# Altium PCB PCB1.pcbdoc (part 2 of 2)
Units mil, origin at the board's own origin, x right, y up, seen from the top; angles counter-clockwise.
Board outline 3543.31 x 2362.2 mil, 2 copper layers (Top Layer, Bottom Layer), stack 62.206 mil thick; 105 components, 91 nets, 439 pads, 301 vias.
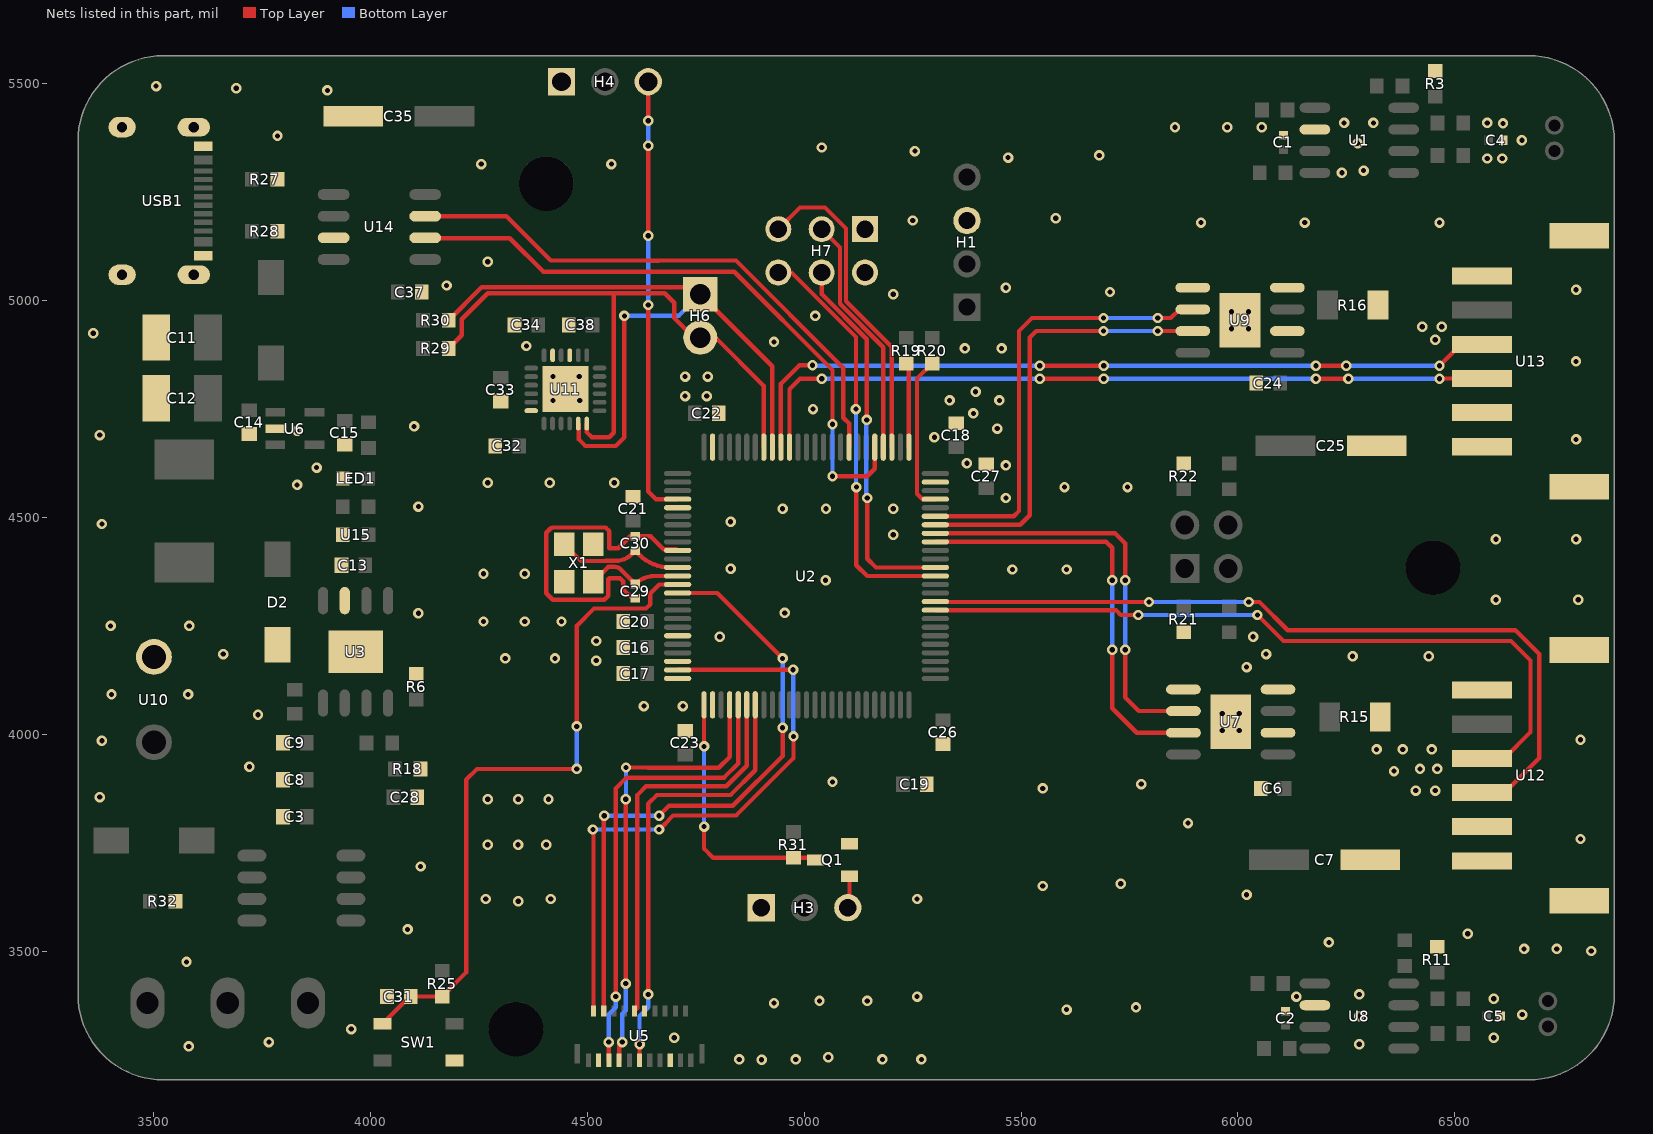
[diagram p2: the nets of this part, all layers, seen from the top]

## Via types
v1: diameter 24.02, hole 12, Top Layer to Bottom Layer, 293 vias
v2: diameter 24, hole 12, Top Layer to Bottom Layer, 8 vias

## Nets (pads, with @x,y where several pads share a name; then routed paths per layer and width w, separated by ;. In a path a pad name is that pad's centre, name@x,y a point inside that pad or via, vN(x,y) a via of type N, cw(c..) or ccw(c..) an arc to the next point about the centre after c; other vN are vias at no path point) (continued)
GND: C1.1 C2.1 C3.2 C4.2 C5.2 C6.1 C7.2 C8.2 C9.1 C11.1 C12.1 C13.1 C14.1 C15.1 C16.2 C17.1 C18.1 C19.1 C20.1 C21.1 C22.1 C23.1 C24.1 C25.2 C26.2 C27.2 C28.1 C29.1 C30.1 C31.1 C32.2 C33.2 C34.1 C35.2 C37.1 C38.1 D2.1 H1.3 H3.1 H4.1 H7.1 H7.2 LED1.2 Q1.2 R3.2 R6.1 R11.2 R15.2 R16.2 R18.1 R21.1 R22.2 R27.1 R28.1 R32.2 SW1.4 U1.2 U2.10 U2.20 U2.27 U2.74 U2.99 U3.7 U3.9 U5.12 U5.17 U6.2 U7.1 U7.9 U8.2 U9.1 U9.9 U10.1 U11.9 U11.11 U11.18 U11.25 U12.2 U12.7 U12.8 U13.2 U13.7 U13.8 U14.3 U15.1 USB1.13 USB1.14 USB1.A1B12 USB1.B1A12 X1.2 X1.4 | length 799.8
  Top Layer w10: C29.1@4610,4313.46 4603.61,4313.46 4582.07,4335 4582.07,4352.93 4575,4360 4550,4360 4548.07,4358.07 4548.07,4319.58 4538.49,4310 4420,4310 4405,4325 4405,4465 4415,4475 4416.51,4475 4418.36,4476.85 4541.64,4476.85 4550,4468.49 4550,4428.95 4571.05,4428.95 4598.64,4456.54 C30.1@4610,4456.54 4645.48,4456.54 4675.17,4426.85 4704.97,4426.85 U2.10@4707.76,4424.06
  other v1: 4901.35,3249.3 4850,3250 4980,3250 5180,3250 5270,3250 5055,3255 3580,3280 6280,3285 3765,3290 4700,3300 6590,3300 3955,3320 6280,3350 6656,3353.35 5605,3365 5765,3370 4930,3380 5035,3385 5145,3385 6590,3390.19 5260,3395 6135,3395 6280,3400 3575,3475 6815,3500 6660,3505 6735.33,3505 6210,3520 6530,3540 4085,3550 4340,3615 4265,3620 4415,3620 5260,3620 6020,3630 5550,3650 5730,3655 4115,3695 4270,3745 4339.76,3745 4405,3745 6790.16,3758.5 5885,3795 4270,3850 4340,3850 4410,3850 3375,3855 6410,3870 6455,3870 5550,3875 5777.01,3885 5065,3890 6360,3915 6420,3920 6460,3920 3720,3925 6320,3965 6380,3965 6447.11,3965 3380,3985 6790.16,3987.49 3740,4045 4630,4065 4720,4065 3402,4091.82 3578.6,4091.82 6020,4155 4520,4170 4310,4175 4425,4175 6264.49,4180 6440,4180 3660,4185 6065,4185 4520,4215 4805,4225 6035,4225 3400,4250 3581.6,4250 4260,4260 4355.24,4260 4440,4260 4110,4279.19 4955,4280 6595,4310 6785,4310 5049.01,4355 4260,4370 4355,4370 5480,4380 5605,4380 4830,4381.88 6595,4450 6780,4450 5205,4460 3380,4485 4830,4490 4950,4520 5050,4520 5205,4520 4110,4525 5465,4545 5600,4570 5745.43,4570 3830,4575 4270,4580 4412.73,4580 4561.61,4580 3875,4615 5465,4620 5375,4625 6780,4680 5300,4685 3375,4690 3830,4700 5445,4705 4100,4710 5390,4740 5020,4750 4420,4770 4482.14,4770 5335,4770 5450,4770 4725,4780 4775,4780 5395,4790 4420,4825 4480.88,4825 4725,4825 4777.24,4825 6779.8,4860 5370.33,4890 5455,4890 4358.93,4895.41 4930,4905 6455,4910 3360,4925 6425,4940 6470,4940 5025,4965 5205,5015 5705,5020 6780,5025 5465,5030 4175,5035 4270,5090 5915,5180 6154.21,5180 6465,5180 5250,5185 5580,5190 6240,5295 6290,5300 4255,5315 4555,5315 6575,5327.98 6609.71,5327.98 5470,5330 5680,5335 5255,5345 5040.39,5353.31 6276.06,5363.14 6655,5370 3785,5380 5855,5400 5975.36,5400 6055,5400 6611.54,5408.95 6245,5410 6312.58,5410 6575,5410 3900,5485 3690,5490 3505,5495
  other v2: 5963.82,4008.82 6003.19,4008.82 5963.82,4048.19 6003.19,4048.19 5985.31,4935.31 6024.68,4935.31 5985.31,4974.68 6024.68,4974.68
I2C1_SCL: H6.1 R30.1 U2.92 U11.23 | length 1672.6
  Top Layer w10: R30.1@4179.66,4955 4255.75,5031.09 4743.91,5031.09 H6.1@4760,5015 4926.26,4848.74 U2.92@4926.26,4662.24 ; U11.23@4478.46,4716.64 4480,4715.1 4480,4680 4495,4665 4565,4665 4585,4685 v1(4585,4965)
  Bottom Layer w10: v1(4585,4965) 4710,4965 H6.1@4760,5015
I2C1_SDA: H6.2 R29.1 U2.93 U11.24 | length 1464.3
  Top Layer w10: R29.1@4179.66,4890 4210,4920.34 4210,4957.07 4270,5017.07 4560.28,5017.07 ; U11.24@4498.14,4716.64 4497.93,4716.44 4497.93,4697.07 4510,4685 4550,4685 4560.28,4695.28 4560.28,5017.07 ; U2.93@4906.57,4662.24 4906.57,4803.43 4795,4915 H6.2@4760,4915 4745,4915 4700,4960 4700,4995 4677.93,5017.07 4560.28,5017.07
LED-(背光开关): U2.24 U5.2 | length 1421.3
  Top Layer w10: v1(4512.27,3780.23) 4513.7,3778.79 U5.2@4513.7,3361.59 ; v1(4665,3780.23) 4673.8,3789.03 4674.52,3789.03 4687.99,3802.49 4687.99,3803.22 4697.4,3812.63 4842.63,3812.63 4975,3945 v1(4975,3995) ; U2.24@4707.76,4148.46 4765,4148.46 4765.33,4148.79 v1(4974.21,4148.79)
  Bottom Layer w10: v1(4512.27,3780.23) v1(4665,3780.23) ; v1(4974.21,4148.79) 4974.21,3995.79 v1(4975,3995)
MOTOR1_IN1: U2.68 U7.2 | length 950
  Top Layer w10: U2.68@5302.24,4463.43 5716.57,4463.43 5740,4440 v1(5740,4355) ; v1(5740,4195) 5740,4085 5771.49,4053.51 U7.2@5874.49,4053.51
  Bottom Layer w10: v1(5740,4195) v1(5740,4355)
MOTOR1_IN2: U2.67 U7.3 | length 971.3
  Top Layer w10: U2.67@5302.24,4443.74 5696.26,4443.74 5710,4430 v1(5710,4355) ; v1(5710,4195) 5710,4060 5766.49,4003.51 U7.3@5874.49,4003.51
  Bottom Layer w10: v1(5710,4195) v1(5710,4355)
MOTOR1_OUT1: U7.6 U12.1
MOTOR1_OUT2: U7.8 U12.6
MOTOR2_IN1: U2.70 U9.2 | length 1034.5
  Top Layer w10: U2.70@5302.24,4502.8 5482.8,4502.8 5495,4515 5495,4930 5525,4960 v1(5690,4960) ; v1(5815,4960) 5845,4960 5865,4980 U9.2@5895.98,4980
  Bottom Layer w10: v1(5690,4960) v1(5815,4960)
MOTOR2_IN2: U2.69 U9.3 | length 1019
  Top Layer w10: U2.69@5302.24,4483.11 5498.11,4483.11 5520,4505 5520,4915 5535,4930 v1(5690,4930) ; v1(5815,4930) U9.3@5895.98,4930
  Bottom Layer w10: v1(5690,4930) v1(5815,4930)
MOTOR2_OUT1: U9.6 U13.1
MOTOR2_OUT2: U9.8 U13.6
OSC_IN: C30.2 U2.12 X1.1 | length 296.5
  Top Layer w10: X1.1@4446.53,4438.31 4485.08,4399.77 4541.64,4399.77 4541.87,4400 4565,4400 ccw(c4565,4452) 4601.77,4415.23 C30.2@4610,4423.46 4619.49,4413.97 ccw(c4690.2,4484.68) 4690.2,4384.68 U2.12@4707.76,4384.68
OSC_OUT: C29.2 U2.13 X1.3 | length 228.9
  Top Layer w10: X1.3@4513.47,4351.69 4547.76,4385.98 4562.62,4385.98 cw(c4562.62,4366.83) 4576.16,4380.38 C29.2@4610,4346.54 cw(c4654.57,4301.97) 4654.57,4365 U2.13@4707.76,4365
RST: C31.2 R25.1 SW1.1 U2.14 | length 1568.5
  Top Layer w10: SW1.1@4027.32,3332.32 4090,3395 4164.66,3395 R25.1@4165,3395.34 4220,3450.34 4220,3895 4245,3920 v1(4475,3920) ; v1(4475,4017.99) 4475,4250 4515,4290 4635,4290 4645,4300 4645,4325 4665.31,4345.31 U2.14@4707.76,4345.31
  Bottom Layer w10: v1(4475,3920) v1(4475,4017.99)
RST_MONITOR: U2.15 U5.4 | length 1449.2
  Top Layer w10: U5.4@4537.32,3361.59 4537.32,3810.78 v1(4538.56,3812.02) ; v1(4665,3812.02) 4687.98,3835 4835,3835 4950,3950 v1(4950,4015) ; U2.15@4707.76,4325.63 4799.37,4325.63 v1(4950,4175)
  Bottom Layer w10: v1(4538.56,3812.02) v1(4665,3812.02) ; v1(4950,4015) v1(4950,4175)
SBUS: H3.3 Q1.1 | length 79.2
  Top Layer w10: H3.3@5100.39,3600 5104.37,3603.98 Q1.1@5104.37,3677.6
SPI1_MISO: U2.31 U5.10 | length 921.8
  Top Layer w10: U5.10@4608.19,3361.59 4614.92,3368.33 4614.92,3859.92 4635,3880 4820,3880 4867.2,3927.2 U2.31@4867.2,4067.76
SPI1_MOSI: U2.32 U5.11 | length 1029.5
  Top Layer w10: U5.11@4620,3248.41 v1(4620,3285) ; v1(4640,3400) 4640,3840 4660,3860 4830,3860 4886.89,3916.89 U2.32@4886.89,4067.76
  Bottom Layer w10: v1(4620,3285) 4620,3350 4640,3370 v1(4640,3400)
SPI1_NSS: U2.29 U5.7 | length 1056
  Top Layer w10: U5.7@4572.76,3248.41 4572.76,3282.76 v1(4580,3290) ; v1(4587.99,3425) v1(4587.99,3850) ; v1(4588.74,3923.27) 4638.74,3923.27 4639.18,3922.83 4802.83,3922.83 4827.83,3947.83 U2.29@4827.83,4072.76
  Bottom Layer w10: v1(4580,3290) 4580,3355 4587.99,3362.99 v1(4587.99,3425) ; v1(4587.99,3850) 4588.74,3850.75 v1(4588.74,3923.27)
SPI1_SCK: U2.30 U5.5 | length 1074.9
  Top Layer w10: v1(4548.9,3290) 4548.9,3248.64 U5.5@4549.13,3248.41 ; v1(4565,3395) 4565,3875 4590,3900 4815,3900 4847.52,3932.52 U2.30@4847.52,4067.76
  Bottom Layer w10: v1(4548.9,3290) 4548.9,3353.9 4565,3370 v1(4565,3395)
SWCLK: R19.2 U2.76 | length 195.7
  Top Layer w10: R19.2@5235,4855.34 5241.22,4849.12 U2.76@5241.22,4662.24
SWDIO: R20.2 U2.72 | length 362.8
  Top Layer w10: R20.2@5295,4855.34 5260,4820.34 5260,4608.46 5259.76,4608.22 5259.76,4554.85 5272.44,4542.17 U2.72@5302.24,4542.17
TE: U5.3
TIM3_CH1: U2.90 U13.3 | length 1740.9
  Top Layer w10: U2.90@4965.63,4662.24 4965.63,4795.63 4990,4820 v1(5040,4820) ; v1(5542.99,4820) v1(5690.6,4820) ; v1(6180,4820) v1(6255,4820) ; v1(6465,4820) 6465.63,4820.63 U13.3@6562.8,4820.63
  Bottom Layer w10: v1(5040,4820) v1(5542.99,4820) ; v1(5690.6,4820) v1(6180,4820) ; v1(6255,4820) v1(6465,4820)
TIM3_CH2: U2.91 U13.4 | length 1801.7
  Top Layer w10: U2.91@4945.94,4662.24 4945.94,4808.46 4988.7,4851.21 v1(5018.79,4851.21) ; v1(5542.99,4850) v1(5690.6,4850) ; v1(6180,4850) v1(6250,4850) ; v1(6465,4850) 6514.37,4899.37 U13.4@6562.8,4899.37
  Bottom Layer w10: v1(5018.79,4851.21) 5020,4850 v1(5542.99,4850) ; v1(5690.6,4850) v1(6180,4850) ; v1(6250,4850) v1(6465,4850)
TIM4_CH1: U2.60 U12.3 | length 1847.9
  Top Layer w10: U2.60@5302.24,4305.94 5303.18,4305 v1(5795,4305) ; v1(6025,4305) 6050,4305 6115,4240 6640,4240 6695,4185 6695,3945 6615.63,3865.63 U12.3@6562.8,3865.63
  Bottom Layer w10: v1(5795,4305) v1(6025,4305)
TIM4_CH2: U2.59 U12.4 | length 1723.2
  Top Layer w10: U2.59@5302.24,4286.26 5718.74,4286.26 5730,4275 v1(5770,4275) ; v1(6045,4275) 6105,4215 6630,4215 6675,4170 6675,4005 6614.37,3944.37 U12.4@6562.8,3944.37
  Bottom Layer w10: v1(5770,4275) v1(6045,4275)
TIM9_CH1: H4.3 U2.4 | length 1020.1
  Top Layer w10: v1(4640,4990) 4640,4560 4657.83,4542.17 U2.4@4707.76,4542.17 ; v1(4640,5150) v1(4640,5357.4) ; v1(4640,5415) H4.3@4640,5505
  Bottom Layer w10: v1(4640,4990) v1(4640,5150) ; v1(4640,5357.4) v1(4640,5415)
TIM9_CH2: U2.5
UART5_RX: U2.83 U14.7 | length 1298.1
  Top Layer w10: U14.7@4125.61,5195 4312.43,5195 4414.93,5092.5 4644.98,5092.5 4645.48,5092.01 4664.52,5092.01 4665.02,5092.5 4842.5,5092.5 5090,4845 5090,4730 5103.43,4716.57 U2.83@5103.43,4662.24
UART5_TX: U2.80 U14.6 | length 1465.2
  Top Layer w10: U14.6@4125.61,5145 4126.43,5144.18 4320.82,5144.18 4398.18,5066.82 4838.18,5066.82 5065,4840 v1(5065,4715) ; v1(5065,4595) 5144.96,4595 5162.48,4612.52 U2.80@5162.48,4662.24
  Bottom Layer w10: v1(5065,4595) v1(5065,4715)
USART2_RX: Q1.3 R31.1 U2.26 | length 597.2
  Top Layer w10: v1(4768.78,3787.01) 4768.78,3736.22 4789.66,3715.34 R31.1@4975,3715.34 5025.29,3715.34 Q1.3@5025.63,3715 ; v1(4768.78,3972.01) U2.26@4768.78,4067.76
  Bottom Layer w10: v1(4768.78,3787.01) v1(4768.78,3972.01)
USART2_TX: U2.25
USART3_RX: H7.3 U2.79 | length 561.6
  Top Layer w10: H7.3@5040,5165 5082.16,5122.84 5082.16,4992.84 5182.17,4892.83 U2.79@5182.17,4662.24
USART3_TX: H7.5 U2.78 | length 745.1
  Top Layer w10: H7.5@4940,5165 4990,5215 5047.85,5215 5096.17,5166.68 5096.17,4998.83 5201.85,4893.15 U2.78@5201.85,4662.24
USART6_RX: H7.4 U2.64 | length 870.1
  Top Layer w10: H7.4@5040,5065 5040,5015.18 5144.14,4911.04 v1(5144.14,4725) ; v1(5145.06,4545) 5145.06,4404.94 5165.32,4384.68 U2.64@5302.24,4384.68
  Bottom Layer w10: v1(5144.14,4725) 5142.99,4723.85 5142.99,4547.07 v1(5145.06,4545)
USART6_TX: H7.6 U2.63 | length 959.9
  Top Layer w10: H7.6@4940,5065 4970.36,5065 5119.08,4916.28 v1(5119.08,4750) ; v1(5120,4570) 5120,4390 5145,4365 U2.63@5302.24,4365
  Bottom Layer w10: v1(5119.08,4750) 5119.08,4570.92 v1(5120,4570)
WKUP: U2.23
pads on no net: SCREW1.1 SCREW2.1 SCREW3.1 SW1.2 SW1.3 U2.1 U2.2 U2.3 U2.9 U2.16 U2.17 U2.18 U2.33 U2.35 U2.36 U2.38 U2.39 U2.40 U2.41 U2.42 U2.43 U2.44 U2.45 U2.46 U2.47 U2.53 U2.54 U2.55 U2.56 U2.57 U2.58 U2.61 U2.62 U2.65 U2.66 U2.71 U2.77 U2.81 U2.82 U2.84 U2.85 U2.86 U2.87 U2.88 U2.89 U2.98 U5.6 U5.15 U5.16 U5.18 U5.19 U5.20 U5.21 U5.22 U5.23 U6.4 U11.1 U11.2 U11.3 U11.4 U11.5 U11.6 U11.7 U11.12 U11.14 U11.15 U11.16 U11.17 U11.19 U11.21 U11.22 U14.4 USB1.A8 USB1.B8

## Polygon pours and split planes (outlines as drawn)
BAT on Top Layer (solid, remove dead copper, pour order 0): 3435,4010 3485,4060 3595,4060 3640,4015 3640,3848.2 3775,3713.2 3870.48,3516.34 3870.48,3464.51 3900,3434.99 3900,3333.17 3881.83,3315 3845,3315 3774.26,3333.17 3774.26,3555.85 3753.69,3600 3690,3600 3435,3855
12V on Top Layer (solid, remove dead copper, pour order 2): 3930,3545 3930,3551.14 3825.74,3770.74 3825,4001.05 3843.95,4020 3895,4020 3920,4045 3920,4100 3935,4115 3990,4115 4010,4095 4010,3955 3950,3895 3950,3795 4035,3710 4035,3590 3990,3545
$1N321 on Top Layer (solid, remove dead copper, pour order 6): 3620,3510 3696.56,3586.56 3761.26,3586.56 3761.26,3550.01 3760,3548.75 3760,3335 3732.79,3307.79 3657.21,3307.79 3620,3345
$1N322 on Top Layer (solid, remove dead copper, pour order 8): 3405,3315 3350,3370 3350,3780 3361.3,3791.3 3436.61,3791.3 3535,3692.92 3535,3335 3515,3315
$1N58 on Top Layer (solid, remove dead copper, pour order 12): 3910,4265 3905,4270 3805,4270 3745,4330 3500,4330 3475,4355 3475,4430 3503.52,4458.52 3806.48,4458.52 3910,4355
5V on Top Layer (solid, remove dead copper, pour order 14): 3805,4680 3805,4615 3750,4560 3514.05,4560 3492.01,4582.05 3492.01,4681.96 3520.04,4710 3565,4710 3565,4976.82 3593.18,5005 3765,5005 3820.64,4949.36 3820.64,4750.64 3795,4725 3685,4725 3685,4665 3745,4665 3760,4680
3V3 on Top Layer (solid, remove dead copper, pour order 18): 3845,4730 3845,4755 3918.99,4828.99 4021.01,4828.99 4021.01,4706.78 4014.23,4700 3914.41,4700 3884.41,4730
BAT_ADC on Top Layer (solid, remove dead copper, pour order 20): 4020,4007.92 4020,3827.04 4080,3827.04 4080,4007.92
MOTOR2_OUT2 on Top Layer (solid, remove dead copper, pour order 22): 6075,5015 6075,5065 6105,5095 6630,5095 6645,5080 6645,5035 6625,5015
MOTOR2_OUT1 on Top Layer (solid, remove dead copper, pour order 24): 6070,4910 6070,4945 6078.73,4953.73 6078.73,4954.91 6370.09,4954.91 6485,4800.33 6485,4715.76 6487.65,4713.1 6611.9,4713.1 6645,4680 6645,4640.33 6628.45,4623.78 6468.3,4623.78 6280,4880 6091.17,4888.83
MOTOR1_OUT2 on Top Layer (solid, remove dead copper, pour order 28): 6050,4115 6050,4135 6060,4145 6640,4145 6650,4135 6650,4085 6625,4060 6495,4060 6472.17,4082.83 6062.17,4082.83 6050,4095
MOTOR1_OUT1 on Top Layer (solid, remove dead copper, pour order 30): 6050,4020 6078.29,4030 6188.79,4030 6398,3820.79 6611.9,3758.11 6615,3755 6625,3755 6650,3730 6650,3696.02 6631.46,3677.48 6453.96,3677.48 6357.49,3722.51 6110,3970 6070,3970 6050,3990
GND on Top Layer (solid, remove dead copper, pour order 36): 3220,5680 3220,3145 6955,3145 6955,5680
GND on Bottom Layer (solid, remove dead copper, pour order 28): 3220,5665 3220,3140 6945,3140 6945,5665
GND on Top Layer (solid, remove dead copper, pour order 34): 3000,5760 3000,3000 7220,3000 7220,5760

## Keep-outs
Board Outline Layer:
  the board outline again, w10

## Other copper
Top Layer:
  region net $1N279: 3727.26,5086.88 3713.12,5072.74 3711.61,5074.13 3710.15,5075.27 3707.31,5077.12 3704.48,5078.98 3703.02,5080.12 3701.51,5081.51 3718.49,5098.49 3719.88,5096.98 3721.02,5095.52 3722.88,5092.69 3724.73,5089.85 3725.87,5088.39
  region net $1N279: 3729.1,5056.76 3717.07,5097.07 3719.77,5094.84 3722.84,5093.15 3726.17,5092.06 3729.64,5091.62 3733.14,5091.83 3736.53,5092.69 3739.7,5094.17 3739.7,5024.94 3739.4,5030.62 3738.49,5036.23 3736.98,5041.71 3734.9,5047 3732.26,5052.04 3729.1,5056.76
  region net 12V: 6127.5,4588.88 6092.5,4588.88 6092.15,4595.63 6091.11,4602.31 6089.39,4608.84 6087.01,4615.16 6083.98,4621.21 6080.35,4626.91 6076.16,4632.21 6071.44,4637.05 6066.25,4641.38 6153.75,4641.38 6148.56,4637.05 6143.84,4632.21 6139.65,4626.91 6136.02,4621.21 6132.99,4615.16 6130.61,4608.84 6128.89,4602.31 6127.85,4595.63 6127.5,4588.88
  region net 12V: 6092.5,4741.12 6127.5,4741.12 6127.85,4734.37 6128.89,4727.69 6130.61,4721.16 6132.99,4714.84 6136.02,4708.79 6139.65,4703.09 6143.84,4697.79 6148.56,4692.95 6153.75,4688.62 6066.25,4688.62 6071.44,4692.95 6076.16,4697.79 6080.35,4703.09 6083.98,4708.79 6087.01,4714.84 6089.39,4721.16 6091.11,4727.69 6092.15,4734.37 6092.5,4741.12
  region net 12V: 6127.5,4816.2 6092.5,4816.2 6092.28,4833.35 6091.92,4842.13 6091.31,4850.4 6090.4,4857.68 6089.8,4860.79 6089.11,4863.48 6088.31,4865.67 6087.4,4867.31 6086.37,4868.34 6085.8,4868.61 6085.2,4868.7 6142.84,4868.7 6141.58,4868.61 6140.39,4868.35 6139.27,4867.93 6138.22,4867.34 6137.23,4866.61 6136.3,4865.73 6134.62,4863.57 6133.16,4860.93 6131.92,4857.86 6130.87,4854.41 6129.99,4850.66 6129.28,4846.64 6128.71,4842.43 6127.96,4833.63 6127.59,4824.74
  region net 12V: 6092.5,3786.12 6127.5,3786.12 6127.85,3779.37 6128.89,3772.69 6130.61,3766.16 6132.99,3759.84 6136.02,3753.79 6139.65,3748.09 6143.84,3742.79 6148.56,3737.95 6153.75,3733.62 6066.25,3733.62 6071.44,3737.95 6076.16,3742.79 6080.35,3748.09 6083.98,3753.79 6087.01,3759.84 6089.39,3766.16 6091.11,3772.69 6092.15,3779.37 6092.5,3786.12
  region net 12V: 6127.5,3635.4 6092.5,3635.4 6092.15,3642.01 6091.11,3648.54 6089.38,3654.92 6086.99,3661.09 6083.96,3666.97 6080.33,3672.5 6076.13,3677.61 6071.42,3682.26 6066.25,3686.38 6153.75,3686.38 6148.58,3682.26 6143.87,3677.61 6139.67,3672.5 6136.04,3666.97 6133.01,3661.09 6130.62,3654.92 6128.89,3648.54 6127.85,3642.01 6127.5,3635.4
  region net 12V: 6127.5,3901.01 6092.5,3889.72 6092.34,3898.71 6092.09,3903.28 6091.7,3907.82 6091.14,3912.3 6090.39,3916.64 6089.41,3920.82 6088.18,3924.77 6086.68,3928.45 6084.87,3931.79 6082.74,3934.77 6080.26,3937.31 6078.87,3938.41 6077.39,3939.38 6075.81,3940.22 6074.12,3940.92 6072.32,3941.48 6070.41,3941.88 6068.39,3942.13 6066.25,3942.22 6132.65,3953.51 6132.43,3949.67 6131.85,3944.68 6130.08,3931.98 6129.13,3924.65 6128.31,3916.92 6127.72,3908.98
  region net $1N19: 6553.62,5365 6553.62,5375 6557.69,5375.37 6561.63,5376.45 6565.31,5378.23 6568.62,5380.63 6568.62,5359.37 6565.31,5361.77 6561.63,5363.55 6557.69,5364.63 6553.62,5365
  region net $1N19: 6578.46,5365 6571.23,5364.71 6564.04,5363.83 6556.95,5362.37 6550,5360.34 6545,5371.42 6550,5384.66 6554.21,5381.78 6558.7,5379.38 6563.43,5377.48 6568.34,5376.11 6573.37,5375.28 6578.46,5375 6578.46,5365
  region net $1N87: 6548.62,3345 6548.62,3355 6552.69,3355.37 6556.63,3356.45 6560.31,3358.23 6563.62,3360.63 6563.62,3339.37 6560.31,3341.77 6556.63,3343.55 6552.69,3344.63 6548.62,3345
  region net $1N87: 6573.46,3355 6568.35,3355.29 6563.3,3356.15 6558.38,3357.57 6553.65,3359.54 6549.17,3362.03 6545,3365 6540,3350.09 6545,3335 6549.17,3337.97 6553.65,3340.46 6558.38,3342.43 6563.3,3343.85 6568.35,3344.71 6573.46,3345 6573.46,3355
  region net I2C1_SDA: 4555.28,4982.07 4554.99,4987.42 4554.13,4992.71 4552.71,4997.88 4550.75,5002.87 4548.26,5007.62 4545.28,5012.07 4560.28,5017.07 4575.28,5012.07 4572.3,5007.62 4569.81,5002.87 4567.85,4997.88 4566.43,4992.71 4565.57,4987.42 4565.28,4982.07 4555.28,4982.07
  region net I2C1_SDA: 4502.93,4697.07 4492.93,4697.07 4492.78,4702.53 4492.62,4706.41 4503.65,4706.41 4503.54,4704.44 4503.29,4702.22 4503.04,4699.77
  region net 3V3: 5007.01,3779.66 5007.01,3769.66 5003.55,3769.34 5000.21,3768.38 4997.11,3766.83 4994.34,3764.73 4992.01,3762.16 4992.01,3787.16 4994.34,3784.59 4997.11,3782.49 5000.21,3780.94 5003.55,3779.98 5007.01,3779.66
  region net 3V3: 5853.59,5338.46 5845.56,5338.14 5837.58,5337.17 5829.7,5335.56 5821.97,5333.33 5814.45,5330.48 5807.18,5327.04 5800.22,5323.02 5793.59,5318.46 5783.59,5351.41 5793.59,5378.46 5800.22,5373.9 5807.18,5369.88 5814.45,5366.44 5821.97,5363.59 5829.7,5361.36 5837.58,5359.75 5845.56,5358.78 5853.59,5358.46 5853.59,5338.46
  region net 3V3: 5853.59,5338.46 5845.56,5338.14 5837.58,5337.17 5829.7,5335.56 5821.97,5333.33 5814.45,5330.48 5807.18,5327.04 5800.22,5323.02 5793.59,5318.46 5783.59,5351.41 5793.59,5378.46 5800.22,5373.9 5807.18,5369.88 5814.45,5366.44 5821.97,5363.59 5829.7,5361.36 5837.58,5359.75 5845.56,5358.78 5853.59,5358.46 5853.59,5338.46
  region net 3V3: 4235,4870 4235.32,4862.6 4236.3,4855.25 4237.91,4848.02 4240.15,4840.95 4243,4834.11 4246.44,4827.55 4250.44,4821.31 4254.97,4815.44 4260,4810 4230,4800 4200,4810 4205.03,4815.44 4209.56,4821.31 4213.56,4827.55 4217,4834.11 4219.85,4840.95 4222.09,4848.02 4223.7,4855.25 4224.68,4862.6 4225,4870
  region net 3V3: 4506.49,4976.64 4516.49,4976.64 4516.81,4973.19 4517.76,4969.85 4519.31,4966.74 4521.41,4963.97 4523.99,4961.64 4498.99,4961.64 4501.56,4963.97 4503.66,4966.74 4505.21,4969.85 4506.16,4973.19
  region net 3V3: 4089.46,4885 4089.46,4895 4092.92,4895.32 4096.26,4896.28 4099.37,4897.83 4102.13,4899.93 4104.46,4902.5 4104.46,4877.5 4102.13,4880.07 4099.37,4882.17 4096.26,4883.72 4092.92,4884.68 4089.46,4885
  region net 3V3: 5363.34,5435 5363.02,5443.04 5362.05,5451.02 5360.45,5458.9 5358.21,5466.62 5355.37,5474.14 5351.92,5481.41 5347.91,5488.38 5343.34,5495 5373.34,5505 5403.34,5495 5398.78,5488.38 5394.77,5481.41 5391.32,5474.14 5388.48,5466.62 5386.24,5458.9 5384.64,5451.02 5383.67,5443.04 5383.34,5435
  region net 3V3: 5363.34,5326.61 5383.34,5329.09 5383.42,5327.2 5383.65,5325.44 5384.02,5323.8 5384.52,5322.27 5385.89,5319.48 5387.67,5316.94 5389.79,5314.54 5392.19,5312.17 5397.49,5307.04 5350.32,5304.56 5352.7,5307.39 5355.04,5309.95 5357.23,5312.36 5359.22,5314.75 5360.9,5317.25 5362.2,5319.97 5362.69,5321.46 5363.05,5323.05 5363.27,5324.76
  region net 3V3: 5957.69,4639.9 5965.89,4645.84 5969.5,4643.56 5973.42,4641.9 5977.55,4640.88 5981.8,4640.54 5962.99,4623.99 5962.65,4628.24 5961.63,4632.38 5959.96,4636.3 5957.69,4639.9
  region net 3V3: 3990,4765.54 4010,4765.54 4010.22,4755.51 4010.89,4745.5 4012.01,4735.54 3977.99,4735.54 3981.54,4739.76 3984.52,4744.4 3986.89,4749.38 3988.61,4754.62 3989.65,4760.03 3990,4765.54
  region net 3V3: 4130.86,4895 4123.45,4895.32 4116.11,4896.3 4108.87,4897.91 4101.81,4900.15 4094.97,4903 4088.4,4906.44 4082.17,4910.44 4076.3,4914.97 4070.86,4920 4060.86,4890 4070.86,4860 4076.3,4865.03 4082.17,4869.56 4088.4,4873.56 4094.97,4877 4101.81,4879.85 4108.87,4882.09 4116.11,4883.7 4123.45,4884.68 4130.86,4885 4130.86,4895
  region net 3V3: 4070.86,4870 4071.18,4861.96 4072.15,4853.98 4073.76,4846.1 4075.99,4838.38 4078.84,4830.86 4082.28,4823.59 4086.3,4816.62 4090.86,4810 4060.86,4800 4030.86,4810 4035.42,4816.62 4039.44,4823.59 4042.88,4830.86 4045.73,4838.38 4047.96,4846.1 4049.57,4853.98 4050.53,4861.96 4050.86,4870
  region net 3V3: 4125.61,5255 4118.18,5255.33 4110.81,5256.3 4103.55,5257.91 4096.46,5260.16 4089.6,5263.01 4083.01,5266.45 4076.75,5270.46 4070.86,5275 4060.86,5245 4070.86,5215 4076.75,5219.54 4083.01,5223.55 4089.6,5226.99 4096.46,5229.84 4103.55,5232.09 4110.81,5233.7 4118.18,5234.67 4125.61,5235 4125.61,5255
  region net 3V3: 4071.3,5235 4071.3,5255 4075.77,5255.1 4080.14,5255.38 4088.34,5256.2 4095.52,5257.03 4098.61,5257.3 4101.3,5257.4 4101.3,5232.6 4098.61,5232.7 4095.52,5232.97 4088.34,5233.8 4080.14,5234.62 4075.77,5234.9
  region net 3V3: 4200,3528.65 4190,3528.65 4189.93,3529.97 4189.72,3531.14 4188.92,3533.2 4187.66,3535.09 4185.99,3537.06 4204.01,3537.06 4202.34,3535.09 4201.08,3533.2 4200.28,3531.14 4200.07,3529.97
  region net 3V3: 4178.77,3475.84 4187.31,3470.24 4185.04,3466.64 4183.37,3462.72 4182.35,3458.58 4182.01,3454.33 4162.86,3470.54 4167.11,3470.88 4171.24,3471.9 4175.16,3473.56 4178.77,3475.84
  region net 3V3: 4205,4730 4205.32,4738.04 4206.29,4746.02 4207.9,4753.9 4210.13,4761.62 4212.98,4769.14 4216.42,4776.41 4220.44,4783.38 4225,4790 4195,4800 4165,4790 4169.56,4783.38 4173.58,4776.41 4177.02,4769.14 4179.87,4761.62 4182.1,4753.9 4183.71,4746.02 4184.68,4738.04 4185,4730
  region net $1N59: 3863.19,4066.89 3863.19,4076.89 3865.76,4076.94 3868.36,4077.12 3870.88,4077.5 3873.21,4078.13 3875.21,4079.07 3876.06,4079.68 3876.79,4080.39 3877.38,4081.21 3877.82,4082.14 3878.1,4083.2 3878.19,4084.39 3878.19,4059.39 3878.1,4060.58 3877.82,4061.64 3877.38,4062.57 3876.79,4063.39 3876.06,4064.1 3875.21,4064.71 3873.21,4065.66 3870.88,4066.29 3868.36,4066.66 3865.76,4066.84
  region net 3V3: 4670,3528.65 4660,3528.65 4659.93,3529.97 4659.72,3531.14 4658.92,3533.2 4657.66,3535.09 4655.99,3537.06 4674.01,3537.06 4672.34,3535.09 4671.08,3533.2 4670.28,3531.14 4670.07,3529.97
  region net 3V3: 4650.43,3375.43 4660.43,3375.43 4660.69,3374.74 4661.34,3374.39 4649.52,3374.39 4650.17,3374.74 4650.43,3375.43
  region net 5V: 4104.91,5390.77 4090.62,5404.76 4093.78,5409.48 4096.42,5414.52 4098.5,5419.81 4100.01,5425.29 4100.92,5430.9 4101.22,5436.58 4136.73,5401.38 4131.06,5401.07 4125.44,5400.16 4119.96,5398.66 4114.67,5396.57 4109.64,5393.93 4104.91,5390.77
  region net 5V: 4269.02,5435 4269.02,5415 4264.18,5414.7 4259.41,5413.82 4254.78,5412.37 4250.37,5410.37 4246.23,5407.84 4242.43,5404.83 4239.02,5401.38 4239.02,5448.62 4242.43,5445.17 4246.23,5442.16 4250.37,5439.63 4254.78,5437.63 4259.41,5436.18 4264.18,5435.3 4269.02,5435
  region net 5V: 4516.75,5467.61 4502.61,5481.75 4503.88,5483.13 4504.94,5484.51 4505.82,5485.91 4506.54,5487.33 4507.54,5490.22 4508.09,5493.23 4508.33,5496.38 4508.39,5499.7 4508.42,5503.22 4508.57,5506.97 4541.97,5473.57 4538.22,5473.42 4534.7,5473.39 4531.38,5473.33 4528.23,5473.09 4525.22,5472.54 4522.33,5471.54 4520.91,5470.82 4519.51,5469.94 4518.13,5468.88
  region net 5V: 3830.3,4866.43 3830.3,4846.43 3825.34,4846.1 3820.48,4845.12 3815.78,4843.51 3811.34,4841.29 3807.23,4838.5 3803.53,4835.2 3800.3,4831.43 3800.3,4881.43 3803.53,4877.66 3807.23,4874.36 3811.34,4871.57 3815.78,4869.35 3820.48,4867.74 3825.34,4866.76 3830.3,4866.43
  region net 3V3: 4089.46,4950 4089.46,4960 4092.92,4960.32 4096.26,4961.28 4099.37,4962.83 4102.13,4964.93 4104.46,4967.5 4104.46,4942.5 4102.13,4945.07 4099.37,4947.17 4096.26,4948.72 4092.92,4949.68 4089.46,4950
  region net 3V3: 4130.86,4960 4123.45,4960.32 4116.11,4961.3 4108.87,4962.91 4101.81,4965.15 4094.97,4968 4088.4,4971.44 4082.17,4975.44 4076.3,4979.97 4070.86,4985 4060.86,4955 4070.86,4925 4076.3,4930.03 4082.17,4934.56 4088.4,4938.56 4094.97,4942 4101.81,4944.85 4108.87,4947.09 4116.11,4948.7 4123.45,4949.68 4130.86,4950 4130.86,4960
  region net 3V3: 4125.61,5085 4118.18,5084.67 4110.81,5083.7 4103.55,5082.09 4096.46,5079.84 4089.6,5076.99 4083.01,5073.55 4076.75,5069.54 4070.86,5065 4060.86,5095 4070.86,5125 4076.75,5120.46 4083.01,5116.45 4089.6,5113.01 4096.46,5110.16 4103.55,5107.91 4110.81,5106.3 4118.18,5105.33 4125.61,5105 4125.61,5085
  region net 3V3: 4071.3,5085 4071.3,5105 4075.77,5105.1 4080.14,5105.38 4088.34,5106.2 4095.52,5107.03 4098.61,5107.3 4101.3,5107.4 4101.3,5082.6 4098.61,5082.7 4095.52,5082.97 4088.34,5083.8 4080.14,5084.62 4075.77,5084.9
  region net 3V3: 4572.28,4498.46 4572.28,4508.46 4579.78,4508.26 4587.28,4508.19 4587.28,4490.96 4584.95,4493.53 4582.19,4495.63 4579.08,4497.18 4575.74,4498.14 4572.28,4498.46
  region net 3V3: 4265,4508.46 4257.6,4508.78 4250.25,4509.76 4243.02,4511.37 4235.95,4513.61 4229.11,4516.46 4222.55,4519.9 4216.31,4523.9 4210.44,4528.43 4205,4533.46 4195,4503.46 4205,4473.46 4210.44,4478.49 4216.31,4483.02 4222.55,4487.02 4229.11,4490.46 4235.95,4493.31 4243.02,4495.55 4250.25,4497.16 4257.6,4498.14 4265,4498.46
  region net 3V3: 4265,4060 4256.96,4059.68 4248.98,4058.71 4241.1,4057.1 4233.38,4054.87 4225.86,4052.02 4218.59,4048.58 4211.62,4044.56 4205,4040 4195,4070 4205,4100 4211.62,4095.44 4218.59,4091.42 4225.86,4087.98 4233.38,4085.13 4241.1,4082.9 4248.98,4081.29 4256.96,4080.32 4265,4080
  region net 3V3: 4435.59,4060 4435.59,4080 4437.64,4080.09 4439.48,4080.31 4442.8,4081 4446.11,4081.69 4447.95,4081.92 4450,4082.01 4450,4057.99 4447.95,4058.08 4446.11,4058.31 4442.8,4059 4439.48,4059.69 4437.64,4059.91
  region net 3V3: 4265,3945 4257.6,3944.68 4250.25,3943.7 4243.02,3942.09 4235.95,3939.85 4229.11,3937 4222.55,3933.56 4216.31,3929.56 4210.44,3925.03 4205,3920 4195,3950 4205,3980 4210.44,3974.97 4216.31,3970.44 4222.55,3966.44 4229.11,3963 4235.95,3960.15 4243.02,3957.91 4250.25,3956.3 4257.6,3955.32 4265,3955
  region net 3V3: 4757.72,3948.14 4757.72,3938.14 4750.18,3937.78 4742.72,3936.69 4742.72,3955.64 4745.05,3953.07 4747.81,3950.97 4750.92,3949.42 4754.26,3948.47 4757.72,3948.14
  region net 3V3: 4692.28,3938.14 4692.28,3948.14 4695.74,3948.47 4699.08,3949.42 4702.19,3950.97 4704.95,3953.07 4707.28,3955.64 4707.28,3936.69 4699.82,3937.78 4692.28,3938.14
  region net 3V3: 4813.15,4027.17 4803.15,4027.17 4803.01,4031.65 4802.7,4035.86 4802.39,4039.48 4802.24,4042.17 4814.06,4042.17 4813.91,4039.48 4813.6,4035.86 4813.29,4031.65
  region net 3V3: 4773.78,4621.65 4763.78,4621.65 4763.64,4626.13 4763.33,4630.34 4763.02,4633.96 4762.87,4636.65 4774.69,4636.65 4774.54,4633.96 4774.23,4630.34 4773.92,4626.13
  region net 3V3: 4744.37,4409.37 4744.37,4399.37 4741.18,4399.23 4738.26,4398.92 4735.64,4398.61 4733.35,4398.46 4733.35,4410.28 4735.64,4410.13 4738.26,4409.82 4741.18,4409.51
  region net 3V3: 4763.54,4493.54 4763.12,4498.48 4763.48,4503.42 4764.62,4508.25 4766.51,4512.84 4769.1,4517.07 4772.32,4520.84 4765.24,4527.92 4760.03,4523.38 4754.4,4519.36 4748.42,4515.9 4742.13,4513.02 4735.6,4510.75 4728.88,4509.12 4722.04,4508.13 4715.13,4507.8 4715.13,4497.8 4722.35,4497.48 4729.51,4496.51 4736.56,4494.91 4743.44,4492.69 4750.09,4489.87 4756.46,4486.46 4763.54,4493.54
  region net 3V3: 5793.59,4730 5793.92,4721.96 5794.89,4713.98 5796.49,4706.1 5798.73,4698.38 5801.57,4690.86 5805.02,4683.59 5809.03,4676.62 5813.59,4670 5783.59,4665 5753.59,4670 5758.16,4676.62 5762.17,4683.59 5765.62,4690.86 5768.46,4698.38 5770.7,4706.1 5772.3,4713.98 5773.27,4721.96 5773.59,4730
  region net 3V3: 5812.06,4890 5808.39,4890.64 5804.89,4891.95 5801.7,4893.89 5798.92,4896.39 5796.65,4899.36 5794.97,4902.69 5793.94,4906.28 5793.59,4910 5783.59,4880 5793.59,4850 5793.94,4853.72 5794.97,4857.31 5796.65,4860.64 5798.92,4863.61 5801.7,4866.11 5804.89,4868.05 5808.39,4869.36 5812.06,4870 5812.06,4890
  region net MOTOR2_IN1: 5857.93,4965.86 5853.02,4975.09 5853.9,4976.31 5854.6,4977.87 5855.81,4981.63 5856.53,4983.64 5857.45,4985.6 5858.69,4987.42 5860.33,4989 5874,4971 5871.91,4969.76 5869.74,4968.99 5867.52,4968.55 5865.33,4968.28 5863.21,4968.02 5861.23,4967.64 5859.45,4966.97 5858.66,4966.48
  region net MOTOR2_IN1: 5831.35,4965 5831.35,4955 5830.03,4954.93 5828.86,4954.72 5826.8,4953.92 5824.91,4952.66 5822.94,4950.99 5822.94,4969.01 5824.91,4967.34 5826.8,4966.08 5828.86,4965.28 5830.03,4965.07
  region net MOTOR2_IN2: 5831.35,4935 5831.35,4925 5830.03,4924.93 5828.86,4924.72 5826.8,4923.92 5824.91,4922.66 5822.94,4920.99 5822.94,4939.01 5824.91,4937.34 5826.8,4936.08 5828.86,4935.28 5830.03,4935.07
  region net MOTOR2_IN2: 5847.9,4925 5847.9,4935 5850.14,4935.14 5852.11,4935.52 5853.89,4936.09 5855.58,4936.83 5858.96,4938.6 5862.9,4940.47 5862.9,4919.53 5858.96,4921.4 5855.58,4923.17 5853.89,4923.91 5852.11,4924.48 5850.14,4924.86
  region net $1N112: 6160.51,4972.5 6160.51,4987.5 6164.84,4987.84 6169.07,4988.83 6173.09,4990.47 6176.81,4992.71 6180.14,4995.49 6183.01,4998.75 6183.01,4961.25 6180.14,4964.51 6176.81,4967.29 6173.09,4969.53 6169.07,4971.17 6164.84,4972.16 6160.51,4972.5
  region net $1N112: 6165.34,4987.5 6165.34,4972.5 6162.06,4972.34 6159.04,4971.91 6156.21,4971.3 6153.52,4970.6 6148.28,4969.29 6145.62,4968.86 6142.84,4968.7 6142.84,4991.3 6145.62,4991.14 6148.28,4990.71 6153.52,4989.4 6156.21,4988.7 6159.04,4988.09 6162.06,4987.66
Bottom Layer:
  region net 5V: 6285,4033.6 6276.96,4033.93 6268.98,4034.9 6261.1,4036.5 6253.38,4038.74 6245.86,4041.58 6238.59,4045.03 6231.62,4049.04 6225,4053.6 6215,4023.6 6225,3993.6 6231.62,3998.17 6238.59,4002.18 6245.86,4005.63 6253.38,4008.47 6261.1,4010.71 6268.98,4012.31 6276.96,4013.28 6285,4013.6
  region net 5V: 6430.59,4013.6 6430.59,4033.6 6432.64,4033.69 6434.48,4033.92 6437.8,4034.61 6441.11,4035.3 6442.95,4035.53 6445,4035.61 6445,4011.6 6442.95,4011.68 6441.11,4011.91 6437.8,4012.6 6434.48,4013.29 6432.64,4013.52

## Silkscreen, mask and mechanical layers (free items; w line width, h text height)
Top Silkscreen Layer:
  drawing of 4 lines, arcs and shapes, not listed
Top Solder Mask Layer:
  drawing of 7 lines, arcs and shapes, not listed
